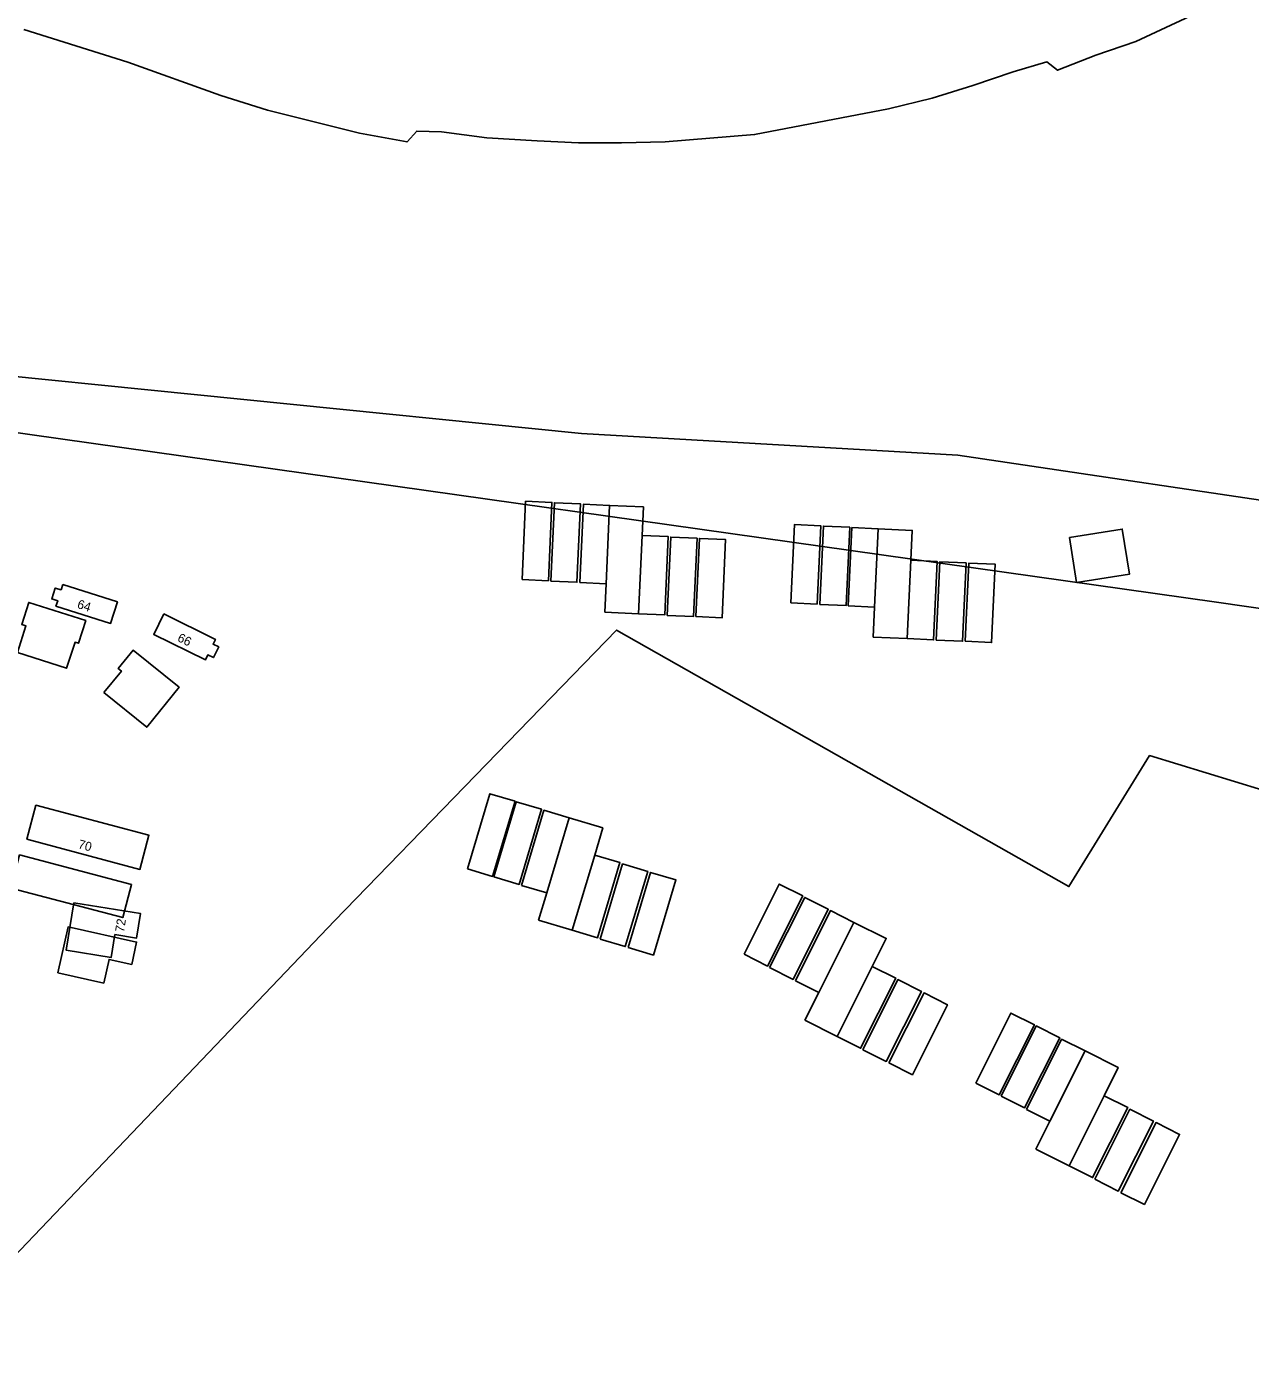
# Model space of a CAD drawing. Extents: x 159451 to 160664, y 388402 to 389723.
# Drawn here: x 160226.5 to 160362.9, y 389415.3 to 389562.7 of the extents above; entities that cross this region are included whole.
import ezdxf

# ---------------------------------------------------------------- set-up
doc = ezdxf.new("R2010")
doc.units = 0
for name, color, linetype in [('IMGEO_Groenvoorziening', 7, 'Continuous'), ('IMGEO_Loofbos', 7, 'Continuous'), ('IMGEO_Pand', 7, 'Continuous'), ('IMGEO_Pand_nummerreeks', 7, 'Continuous'), ('IMGEO_Pand_vergunning_verleend', 7, 'Continuous'), ('IMGEO_Voetpad_open', 7, 'Continuous')]:
    doc.layers.add(name, color=color, linetype=linetype)

msp = doc.modelspace()

# ---------------------------------------------------------------- linework, layer by layer
at = {"layer": 'IMGEO_Groenvoorziening'}
for points in [[(160213.01, 389524.85), (160288.33, 389517.26), (160330.25, 389514.87), (160373.24, 389508.47), (160381.22, 389508.86), (160387.7, 389510.08), (160392.44, 389513.68), (160398.18, 389520.4), (160408.17, 389541.3), (160416.84, 389550.74), (160424.25, 389555.01), (160437.38, 389558.27), (160450.65, 389560.23), (160463.34, 389565.62), (160491.45, 389579.98), (160493.54, 389581.39), (160498.44, 389583.72), (160502.06, 389585.01), (160505.77, 389586.04)], [(160358.94, 389565.1), (160350.1, 389560.99), (160345.65, 389559.45), (160341.38, 389557.76), (160340.2, 389558.69), (160336.43, 389557.58), (160331.93, 389556.05), (160327.39, 389554.65), (160322.52, 389553.46), (160307.62, 389550.59), (160297.66, 389549.79), (160292.8, 389549.67), (160288, 389549.69), (160283.38, 389549.89), (160277.77, 389550.22), (160272.71, 389550.9), (160269.96, 389550.98), (160268.89, 389549.78), (160263.6, 389550.76), (160253.35, 389553.3), (160248.12, 389554.95), (160237.78, 389558.66), (160226.18, 389562.3)], [(160365.79, 389497.5), (160359.11, 389498.45), (160213.4, 389519.05)], [(160193.04, 389391.96), (160260.8, 389462.93), (160292.24, 389495.35), (160342.65, 389466.76), (160351.63, 389481.36), (160405.31, 389464.95)], [(160370.8, 389390.89), (160398.61, 389438.15), (160405.31, 389464.95), (160351.63, 389481.36), (160342.65, 389466.76), (160292.24, 389495.35), (160260.8, 389462.93), (160193.04, 389391.96)]]:
    msp.add_lwpolyline(points, dxfattribs=at)
for points in [[(160230.52, 389500.43), (160236.61, 389498.5), (160235.85, 389496.1), (160229.76, 389498.03), (160229.95, 389498.62), (160229.29, 389498.83), (160229.67, 389500.04), (160230.33, 389499.84)], [(160241.79, 389497.15), (160247.52, 389494.32), (160247.26, 389493.77), (160247.89, 389493.47), (160247.31, 389492.28), (160246.68, 389492.59), (160246.41, 389492.03), (160240.66, 389494.87)], [(160227.53, 389475.83), (160240.12, 389472.47), (160239.12, 389468.67), (160226.52, 389472.04)], [(160231.75, 389464.94), (160239.18, 389463.75), (160238.75, 389461.01), (160236.32, 389461.4), (160235.91, 389458.85), (160230.91, 389459.66)]]:
    msp.add_lwpolyline(points, close=True, dxfattribs=at)
at = {"layer": 'IMGEO_Loofbos'}
msp.add_lwpolyline([(160226.18, 389562.3), (160237.78, 389558.66), (160248.12, 389554.95), (160253.35, 389553.3), (160263.6, 389550.76), (160268.89, 389549.78), (160269.96, 389550.98), (160272.71, 389550.9), (160277.77, 389550.22), (160283.38, 389549.89), (160288, 389549.69), (160292.8, 389549.67), (160297.66, 389549.79), (160307.62, 389550.59), (160322.52, 389553.46), (160327.39, 389554.65), (160331.93, 389556.05), (160336.43, 389557.58), (160340.2, 389558.69), (160341.38, 389557.76), (160345.65, 389559.45), (160350.1, 389560.99), (160358.94, 389565.1)], dxfattribs=at)
at = {"layer": 'IMGEO_Pand'}
for points in [[(160230.52, 389500.43), (160230.33, 389499.84), (160229.67, 389500.04), (160229.29, 389498.83), (160229.95, 389498.62), (160229.76, 389498.03), (160235.85, 389496.1), (160236.61, 389498.5)], [(160241.79, 389497.15), (160240.66, 389494.87), (160246.41, 389492.03), (160246.68, 389492.59), (160247.31, 389492.28), (160247.89, 389493.47), (160247.26, 389493.77), (160247.52, 389494.32)], [(160240.12, 389472.47), (160227.53, 389475.83), (160226.52, 389472.04), (160239.12, 389468.67)], [(160239.18, 389463.75), (160231.75, 389464.94), (160230.91, 389459.66), (160235.91, 389458.85), (160236.32, 389461.4), (160238.75, 389461.01)]]:
    msp.add_lwpolyline(points, close=True, dxfattribs=at)
at = {"layer": 'IMGEO_Pand_vergunning_verleend'}
for points in [[(160281.7, 389500.98), (160282.1, 389509.71), (160285.03, 389509.58), (160284.63, 389500.85)], [(160284.9, 389500.82), (160285.3, 389509.55), (160288.22, 389509.42), (160287.82, 389500.68)], [(160288.14, 389500.65), (160288.54, 389509.38), (160291.46, 389509.25), (160291.06, 389500.52)], [(160290.92, 389497.35), (160291.06, 389500.52), (160291.46, 389509.25), (160295.22, 389509.08), (160295.07, 389505.91), (160294.67, 389497.17)], [(160311.65, 389498.39), (160312.05, 389507.12), (160314.98, 389506.99), (160314.58, 389498.26)], [(160314.89, 389498.22), (160315.29, 389506.95), (160318.22, 389506.81), (160317.82, 389498.08)], [(160318.06, 389498.05), (160318.46, 389506.78), (160321.39, 389506.64), (160320.99, 389497.91)], [(160320.84, 389494.57), (160320.99, 389497.91), (160321.39, 389506.64), (160325.18, 389506.47), (160325.03, 389503.13), (160324.63, 389494.4)], [(160342.7, 389505.69), (160348.58, 389506.62), (160349.38, 389501.57), (160343.5, 389500.64)], [(160294.67, 389497.17), (160295.07, 389505.91), (160298, 389505.77), (160297.6, 389497.04)], [(160297.88, 389496.99), (160298.27, 389505.72), (160301.2, 389505.59), (160300.8, 389496.85)], [(160301.06, 389496.85), (160301.46, 389505.58), (160304.39, 389505.45), (160303.99, 389496.71)], [(160324.63, 389494.4), (160325.03, 389503.13), (160327.96, 389503), (160327.56, 389494.26)], [(160327.86, 389494.24), (160328.26, 389502.97), (160331.18, 389502.84), (160330.79, 389494.11)], [(160331.1, 389494.1), (160331.5, 389502.83), (160334.43, 389502.69), (160334.03, 389493.96)], [(160225.46, 389492.87), (160226.41, 389495.84), (160225.95, 389495.99), (160226.73, 389498.44), (160233.07, 389496.41), (160232.26, 389493.88), (160231.88, 389494), (160230.95, 389491.1)], [(160235.1, 389488.38), (160237.05, 389490.78), (160236.7, 389491.06), (160238.36, 389493.11), (160243.48, 389488.97), (160239.87, 389484.51)], [(160275.62, 389468.73), (160278.12, 389477.11), (160280.92, 389476.27), (160278.42, 389467.89)], [(160278.56, 389467.83), (160281.06, 389476.21), (160283.87, 389475.37), (160281.37, 389467)], [(160281.64, 389466.89), (160284.14, 389475.26), (160286.95, 389474.42), (160284.45, 389466.05)], [(160283.54, 389463.01), (160284.45, 389466.05), (160286.95, 389474.42), (160290.7, 389473.3), (160289.8, 389470.26), (160287.3, 389461.89)], [(160224.72, 389466.58), (160225.7, 389470.29), (160238.18, 389466.99), (160237.2, 389463.29)], [(160287.3, 389461.89), (160289.8, 389470.26), (160292.6, 389469.43), (160290.11, 389461.05)], [(160290.41, 389460.9), (160292.91, 389469.28), (160295.71, 389468.44), (160293.21, 389460.07)], [(160293.53, 389459.95), (160296.03, 389468.33), (160298.84, 389467.49), (160296.34, 389459.11)], [(160306.45, 389459.21), (160310.36, 389467.03), (160312.98, 389465.71), (160309.07, 389457.9)], [(160309.29, 389457.73), (160313.21, 389465.54), (160315.83, 389464.23), (160311.91, 389456.41)], [(160312.16, 389456.26), (160316.07, 389464.08), (160318.69, 389462.76), (160314.77, 389454.95)], [(160313.22, 389451.85), (160314.77, 389454.95), (160318.69, 389462.76), (160322.28, 389460.97), (160320.72, 389457.86), (160316.81, 389450.05)], [(160229.96, 389457.14), (160231.1, 389462.26), (160238.75, 389460.56), (160238.2, 389458.08), (160235.67, 389458.64), (160235.08, 389456)], [(160316.81, 389450.05), (160320.72, 389457.86), (160323.34, 389456.55), (160319.43, 389448.73)], [(160319.67, 389448.57), (160323.58, 389456.38), (160326.2, 389455.07), (160322.29, 389447.26)], [(160322.58, 389447.09), (160326.5, 389454.9), (160329.11, 389453.59), (160325.2, 389445.77)], [(160332.26, 389444.85), (160336.18, 389452.66), (160338.8, 389451.35), (160334.88, 389443.54)], [(160335.09, 389443.4), (160339.01, 389451.22), (160341.62, 389449.9), (160337.71, 389442.09)], [(160337.91, 389441.92), (160341.82, 389449.74), (160344.44, 389448.43), (160340.53, 389440.61)], [(160338.96, 389437.48), (160340.53, 389440.61), (160344.44, 389448.43), (160348.15, 389446.57), (160346.58, 389443.44), (160342.67, 389435.63)], [(160342.67, 389435.63), (160346.58, 389443.44), (160349.2, 389442.13), (160345.28, 389434.32)], [(160345.53, 389434.12), (160349.45, 389441.93), (160352.07, 389440.62), (160348.15, 389432.81)], [(160348.44, 389432.63), (160352.35, 389440.45), (160354.97, 389439.13), (160351.05, 389431.32)]]:
    msp.add_lwpolyline(points, close=True, dxfattribs=at)
at = {"layer": 'IMGEO_Voetpad_open'}
for points in [[(160213.4, 389519.05), (160359.11, 389498.45), (160365.79, 389497.5), (160376.55, 389495.98), (160386.54, 389496.1), (160393.61, 389498.23), (160400, 389502.27), (160405.5, 389509.12), (160410.4, 389517.69), (160412.55, 389528.89), (160414.23, 389535.28), (160420.07, 389541.8), (160428.15, 389546.06), (160437.75, 389548.31), (160443.39, 389548.82), (160453.33, 389551.39), (160465.31, 389557.48), (160487.54, 389570.96)], [(160463.34, 389565.62), (160450.65, 389560.23), (160437.38, 389558.27), (160424.25, 389555.01), (160416.84, 389550.74), (160408.17, 389541.3), (160398.18, 389520.4), (160392.44, 389513.68), (160387.7, 389510.08), (160381.22, 389508.86), (160373.24, 389508.47), (160330.25, 389514.87), (160288.33, 389517.26), (160213.01, 389524.85)]]:
    msp.add_lwpolyline(points, dxfattribs=at)

# ---------------------------------------------------------------- texts
at = {"layer": 'IMGEO_Pand_nummerreeks'}
for s, rotation, p in [('64', 342.4102, (160232.05, 389497.83)), ('66', 333.7299, (160243.21, 389494.17)), ('70', 345.0458, (160232.16, 389471.05)), ('72', 81.0621, (160237.33, 389461.62))]:
    msp.add_text(s, height=1, rotation=rotation, dxfattribs=at).set_placement(p)

doc.saveas('drawing.dxf')
